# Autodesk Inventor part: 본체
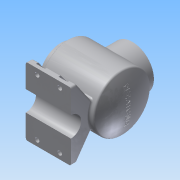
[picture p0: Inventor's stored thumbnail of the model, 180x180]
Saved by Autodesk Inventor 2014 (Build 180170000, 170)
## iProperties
Created: 2017-04
Part Number: 본체
Material: 알루미늄 6061
Document SubType Name: Modeling
Designer: 학생용
Density: 2.71 g/cm^3
Appearance: 알루미늄 - 평지
Mass: 1670.69 g
Surface Area: 1066.88 cm^2
Volume: 616.49 cm^3
Author: 학생용
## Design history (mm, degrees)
sketch "스케치1"
  geometry: L1 (-60, 0)-(60, 0); L2 (-60, 0)-(-60, 38); L3 (-60, 38)-(-48, 38); L4 (-48, 38)-(-48, 50); L5 (-48, 50)-(48.336, 50); L6 (-38, 40)-(41.916, 40); L7 (-38, 40)-(-38, 27); L8 (-38, 27)-(-60, 27); A1 r 113 centre (-53, 0) between (60, 0) and (48.336, 50); A2 r 103 centre (-53, 0) between (50, 0) and (41.916, 40); 2 further points
  constraints: 16 end point, 4 perpendicular, 4 point on circle, 3 parallel, 3 point on line, 2 centre point, 1 coincident, 1 horizontal, 1 midpoint
  dimensions: "d0" = 226 diameter of A1; "d1" = 10 radial gap between concentric circles of A1 A2; "d2" = 100 diameter of L5 L1; "d3" = 54 diameter of L8 L1; "d4" = 76 diameter of L3 L1; "d5" = 80 diameter of L6 L1; "d6" = 22 distance of L7.end L8.end; "d7" = 12 distance of L2.end L3.end; "d15" = 108 distance from line of L1.end L4
revolve "회전1" sketch "스케치1" stored, may be unused: angle "d9" = 90 deg
node "작업 평면1"
sketch "스케치2"
  geometry: L1 (-40, 50)-(40, 50); L2 (40, 50)-(40, -50); L3 (40, -50)-(-40, -50); L4 (-40, -50)-(-40, 50); L5 (48, 50)-(48, -50) reference; L6 (48, 50)-(48, -50) reference; L7 (-48.336, 50)-(-48.336, -50) reference; L8 (-48.336, 50)-(-48.336, -50) reference; L9 (60, 38)-(60, -38) reference; L10 (60, 38)-(60, -38) reference; L11 (48, 38)-(48, -38) reference; A1 r 113 centre (53, 0) between (-48.336, 50) and (-48.336, -50) reference; 2 further points
  constraints: 8 end point, 2 parallel, 1 horizontal, 1 horizontal alignment, 1 midpoint, 1 perpendicular
  dimensions: "d11" = 80 distance of L2.end L3.end; "d12" = 100 distance of L1.end L2.end; "d14" = 8 distance between parallel lines of L11 L2
  node "투영된 루프1"
  node "투영된 루프2"
node "작업 평면2"
sketch "스케치3"
  geometry: L1 (-21.584, -45.101)-(-60, -72); L2 (-60, -72)-(-60, -82); L3 (60, -82)-(60, -72); L4 (60, -72)-(21.584, -45.101); L5 (-60, -82)-(-18, -82); L6 (18, -82)-(60, -82); C1 r 27 at (0, 0) reference; A1 r 50 centre (0, 0) between (-21.584, -45.101) and (21.584, -45.101) reference; A2 r 18 centre (0, -82) between (18, -82) and (-18, -82); 2 further points
  constraints: 12 end point, 4 perpendicular, 4 point on circle, 2 horizontal alignment, 1 centre point, 1 coincident, 1 collinear, 1 vertical, 1 vertical alignment
  dimensions: "d17" = 55 deg angle of L3 L4; "d18" = 10 distance of L3.start L3.end; "d19" = 18 radius of A2; "d22" = 120 distance between parallel lines of L3 L2; "d27" = 82 distance from line of L6 point (0, 0); "d28" = 55 deg angle of L1 L3; "d29" = 42 distance from line of L6.start L3
extrude "돌출1" join sketch "스케치3" distance "d30" = 80; taper "d31" = 0 deg
node "작업 평면3"
sketch "스케치4"
  geometry: L1 (-80, 43.029)-(0, 43.029) reference; L2 (0, 43.029)-(0, 0) reference; L3 (0, 0)-(-80, 0) reference; L4 (-80, 0)-(-80, 43.029) reference; L5 (-80, 120)-(0, 120) reference; L6 (0, 120)-(0, 76.971) reference; L7 (0, 76.971)-(-80, 76.971) reference; L8 (-80, 76.971)-(-80, 120) reference; L9 (-68, 110)-(-68, 120); L10 (-52, 110)-(-52, 120); L11 (-28, 110)-(-28, 120); L12 (-12, 110)-(-12, 120); L13 (-28, 10)-(-28, 0); L14 (-12, 10)-(-12, 0); L15 (-52, 10)-(-52, 0); L16 (-68, 10)-(-68, 0); A1 r 8 centre (-60, 110) between (-68, 110) and (-52, 110); A2 r 8 centre (-20, 110) between (-28, 110) and (-12, 110); A3 r 8 centre (-60, 10) between (-52, 10) and (-68, 10); A4 r 8 centre (-20, 10) between (-28, 10) and (-12, 10); 1 further point
  constraints: 16 end point, 8 point on circle, 8 point on line, 8 tangent, 6 parallel, 4 centre point, 3 equal radius, 2 horizontal alignment, 2 perpendicular, 2 vertical alignment
  dimensions: "d33" = 16 diameter of A1; "d34" = 10 distance from line of L5 A1.centre; "d35" = 20 distance from line of L8 A1.centre; "d37" = 40 distance of A4.centre A3.centre; "d38" = 10 distance from line of L3 A3.centre
extrude "돌출2" cut sketch "스케치4" distance "d39" = 40; taper "d40" = 0 deg
hole "구멍1" diameter "d43" = 8; stored, may be unused: countersink angle "d47" = 90 deg, drill point angle "d49" = 118 deg; dims "d44" = 6, "d45" = 4, "d46" = 2, "d48" = 8, "d56" = 10, "d57" = 10
fillet "모깎기1" dims "d58" = 3
fillet "모깎기2" dims "d59" = 3
fillet "모깎기3" dims "d60" = 3
chamfer "모따기1" distance "d61" = 1; stored, may be unused: second distance "d62" = 2, angle "d63" = 45 deg
node "작업 평면4"
sketch "스케치5"
  geometry: L1 (20, 56)-(20, -20) reference; C1 r 38 at (-42, 18); 1 further point
  constraints: 1 centre point, 1 horizontal alignment, 1 midpoint
  dimensions: "d65" = 62 distance from line of L1 C1.centre; "d67" = 76 diameter of C1
extrude "돌출3" join sketch "스케치5" stored distance "d68" = 40; taper "d69" = 0 deg
sketch "스케치6"
  geometry: C1 r 38 at (0, 0) reference; C2 r 27 at (0, 0); 1 further point
  constraints: 1 centre point, 1 coincident
  dimensions: "d70" = 54 diameter of C2
extrude "돌출4" cut sketch "스케치6" distance "d71" = 40; taper "d72" = 0 deg
sketch "스케치7"
  geometry: C1 r 38 at (0, 0) reference; 1 further point
  constraints: 1 vertical alignment
  dimensions: "d73" = 32.5 distance of C1.centre point (0, 32.5)
hole "구멍2" sketch "스케치7" at (0, 32.5) diameter "d74" = 3.242; stored, may be unused: countersink angle "d78" = 90 deg, drill point angle "d80" = 118 deg; dims "d75" = 8, "d76" = 4, "d77" = 2, "d79" = 10
sketch "스케치8"
  geometry: C1 r 27 at (0, 0) reference; 2 further points
  constraints: 1 vertical alignment
  dimensions: "d84" = 32.5 distance of C1.centre point (0, 32.5)
hole "구멍3" sketch "스케치8" at (0, 32.5) diameter "d85" = 3.242; stored, may be unused: countersink angle "d89" = 90 deg, drill point angle "d91" = 118 deg; dims "d86" = 8, "d87" = 4, "d88" = 2, "d90" = 10
node "작업 평면5"
sketch "스케치9"
  geometry: C1 r 48.282 at (0, 0) reference; 2 further points
  constraints: 1 coincident, 1 other
feature "엠보싱1" sketch "스케치9" dims "d0" = 226, "d1" = 10, "d2" = 100, "d3" = 54, "d4" = 76, "d5" = 80, "d6" = 22, "d7" = 12, "d15" = 108, "d96" = 0.5, "d97" = 0
fillet "모깎기4" dims "d98" = 3
chamfer "모따기2" distance "d99" = 1; stored, may be unused: second distance "d100" = 2, angle "d101" = 45 deg
node "솔리드1"
pattern_linear "직사각형 패턴1" dims "d52" = 40
pattern_circular "원형 패턴1" dims angle "d82" = 360 deg
pattern_circular "원형 패턴2" dims angle "d93" = 360 deg
node "절단 모서리 투영1"
node "절단 모서리 투영2"
other parameters: "d10" = -82, "d16" = -8, "d21" = 82, "d32" = -6, "d64" = -147
